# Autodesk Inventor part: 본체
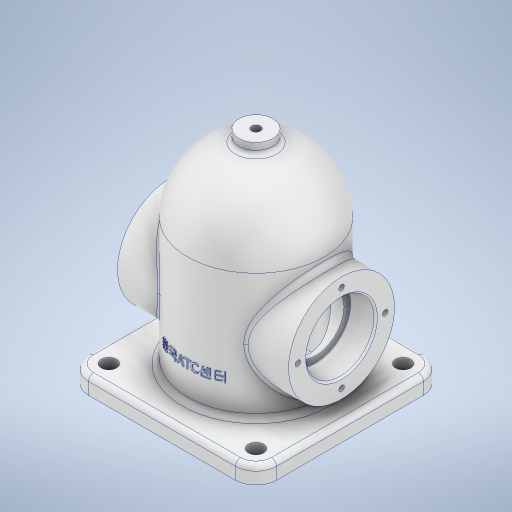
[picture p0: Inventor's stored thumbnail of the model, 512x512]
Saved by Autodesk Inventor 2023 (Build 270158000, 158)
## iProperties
Created: 2025-04
Part Number: 본체
Material: 알루미늄 6061
Document SubType Name: Modeling
Designer: Admin
Density: 2.7 g/cm^3
Appearance: 알루미늄 - 평지
Author: Admin
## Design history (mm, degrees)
node "작업 평면1"
sketch "스케치1"
  geometry: L1 (-55, 55)-(55, 55); L2 (55, 55)-(55, -55); L3 (55, -55)-(-55, -55); L4 (-55, -55)-(-55, 55); L5 (-55, 55)-(55, -55); L6 (55, 55)-(-55, -55); 1 further point
  constraints: 12 end point, 2 midpoint, 2 parallel, 1 horizontal, 1 perpendicular
  dimensions: "d1" = 110 distance of L2.end L3.end; "d2" = 110 distance of L1.end L2.end
extrude "돌출1" new body sketch "스케치1" distance "d3" = 10; taper "d4" = 0 deg
sketch "스케치2"
  geometry: L1 (43, -43)-(-43, -43); L2 (-43, -43)-(-43, 43); L3 (-43, 43)-(43, 43); L4 (43, 43)-(43, -43); L5 (43, -43)-(-43, 43); L6 (-43, -43)-(43, 43); 5 further points
  constraints: 12 end point, 4 coincident, 2 midpoint, 2 parallel, 1 horizontal, 1 perpendicular
  dimensions: "d5" = 86 distance of L2.end L3.end; "d6" = 86 distance of L1.end L2.end
hole "구멍1" sketch "스케치2" at (-43, -43), (-43, 43), (43, -43), (43, 43) diameter "d7" = 9; stored, may be unused: countersink angle "d11" = 90 deg, drill point angle "d13" = 0 deg; dims "d8" = 8, "d9" = 4, "d10" = 2, "d12" = 10
sketch "스케치12"
  geometry: C1 r 40 at (0, 0); 1 further point
  constraints: 1 centre point, 1 coincident
  dimensions: "d50" = 40 radius of C1
extrude "돌출4" join sketch "스케치12" distance "d51" = 74; taper "d52" = 0 deg
sketch "스케치15"
  geometry: L1 (36, -40)-(36, 40) reference; L2 (-72.8, 0)-(100.8, 0) reference; A1 r 40 centre (36, 0) between (36, -40) and (36, 40); 1 further point
  constraints: 2 point on circle, 1 centre point, 1 midpoint
revolve "회전3" sketch "스케치15" stored, may be unused: angle "d53" = 90 deg
node "작업 평면3"
sketch "스케치17"
  geometry: L1 (-48, 55)-(-48, -55) reference; C1 r 31 at (0, 0); 1 further point
  constraints: 1 centre point, 1 coincident
  dimensions: "d61" = 62 diameter of C1; "d62" = 48 distance from line of L1 C1.centre
extrude "돌출6" join sketch "스케치17" stored distance "d63" = 32; taper "d64" = 0 deg
sketch "스케치18"
  geometry: C1 r 20 at (0, 0); 1 further point
  constraints: 1 centre point, 1 coincident
  dimensions: "d65" = 40 diameter of C1
extrude "돌출7" cut sketch "스케치18" distance "d66" = 15; taper "d67" = 0 deg
sketch "스케치20"
  geometry: L1 (-40, -38)-(-40, 36) reference; L2 (40, -38)-(40, 36) reference; L3 (-32, 36)-(-32, -48); L4 (55, -48)-(-55, -48) reference; L5 (0, -72.8)-(0, 100.8) reference; L6 (0, 68)-(0, -48); A1 r 40 centre (0, 36) between (40, 36) and (-40, 36) reference; A2 r 32 centre (0, 36) between (0, 68) and (-32, 36); 1 further point
  constraints: 4 end point, 3 point on line, 2 point on circle, 1 centre point, 1 midpoint, 1 vertical
  dimensions: "d69" = 32 radius of A2; "d70" = 8 distance between parallel lines of L1 L3
revolve "회전4" sketch "스케치20" stored, may be unused: angle "d71" = 360 deg
sketch "스케치21"
  geometry: C1 r 16.5 at (0, 0); 1 further point
  constraints: 1 centre point, 1 coincident
  dimensions: "d72" = 33 diameter of C1
extrude "돌출8" cut sketch "스케치21" stored distance "d73" = 15; taper "d74" = 0 deg
node "작업 평면4"
sketch "스케치22"
  geometry: C1 r 10 at (0, 0); 1 further point
  constraints: 1 centre point, 1 coincident
  dimensions: "d76" = 20 diameter of C1
extrude "돌출9" join sketch "스케치22" stored distance "d77" = 10; taper "d78" = 0 deg
sketch "스케치23"
  geometry: 2 further points
  constraints: 2 coincident
hole "구멍2" sketch "스케치23" at (0, 0) diameter "d79" = 5.1881; stored, may be unused: countersink angle "d83" = 90 deg, drill point angle "d85" = 0 deg; dims "d80" = 12, "d81" = 4, "d82" = 2, "d84" = 8
fillet "모깎기2" dims "d86" = 3
fillet "모깎기3" dims "d87" = 3
fillet "모깎기4" dims "d88" = 12
fillet "모깎기5" dims "d89" = 3
sketch "스케치24" dims "d90" = 51
  geometry: 3 further points
  constraints: 2 coincident, 2 vertical alignment, 2 other
hole "구멍3" sketch "스케치24" at (0, 25.5) diameter "d91" = 3.242; stored, may be unused: countersink angle "d95" = 90 deg, drill point angle "d97" = 118 deg; dims "d92" = 8, "d93" = 4, "d94" = 2, "d96" = 10
node "작업 평면5"
sketch "스케치25"
  geometry: L1 (-43, -48)-(43, -48) reference; 2 further points
  constraints: 1 vertical alignment, 1 other
  dimensions: "d103" = 30 distance from line of L1 point (0, -18)
feature "엠보싱1" sketch "스케치25" dims "d1" = 110, "d2" = 110, "d104" = 0.5, "d105" = 0
fillet "모깎기7" dims "d106" = 0.3
chamfer "모따기1" distance "d107" = 1; stored, may be unused: second distance "d108" = 2, angle "d109" = 45 deg
node "솔리드1"
mirror "미러1"
mirror "미러2"
mirror "미러3"
pattern_circular "원형 패턴1" dims angle "d99" = 360 deg
mirror "미러4"
feature "A9D066F2-1C7D-4E18-AEED-F7BC21143FA4" dims "d7" = 9, "d8" = 8, "d9" = 4, "d10" = 2, "d11" = 90 deg, "d12" = 10, "d13" = 0
other parameters: "d0" = -48, "d75" = -129
